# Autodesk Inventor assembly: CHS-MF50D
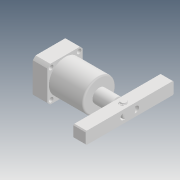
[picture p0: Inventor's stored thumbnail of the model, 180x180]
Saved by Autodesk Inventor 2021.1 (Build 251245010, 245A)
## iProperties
Created: 2019-04
Part Number: CHS-MF50D
Description: STEP AP203
Document SubType Name: Assembly
Designer: user
Title: chs-mf50d_asm.STEP
Revision Number: ÈÎºÎ
Sending System: SolidWorks 2017
Preprocessor: SwSTEP 2.0
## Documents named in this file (12)
- D:\Vault_2016\Projekty\Clamptek\Hydraulic\CHS\CHS-50\Inventor\CHS-MF50D\CHS-MF50D.iam
- D:\Vault_2016\Projekty\Clamptek\Hydraulic\CHS\CHS-50\Inventor\CHS-MF50D\CHS-MF50BT_1.ipt
- D:\Vault_2016\Projekty\Clamptek\Hydraulic\CHS\CHS-50\Inventor\CHS-MF50D\CHS-50DHSG_4.ipt
- D:\Vault_2016\Projekty\Clamptek\Hydraulic\CHS\CHS-50\Inventor\CHS-MF50D\M6_2.ipt
- D:\Vault_2016\Projekty\Clamptek\Hydraulic\CHS\CHS-50\Inventor\CHS-MF50D\PRT0002_1.ipt
- D:\Vault_2016\Projekty\Clamptek\Hydraulic\CHS\CHS-50\Inventor\CHS-MF50D\M6LM_1.ipt
- D:\Vault_2016\Projekty\Clamptek\Hydraulic\CHS\CHS-50\Inventor\CHS-MF50D\PRT0003_1.ipt
- D:\Vault_2016\Projekty\Clamptek\Hydraulic\CHS\CHS-50\Inventor\CHS-MF50D\PRT0001_1.ipt
- D:\Vault_2016\Projekty\Clamptek\Hydraulic\CHS\CHS-50\Inventor\CHS-MF50D\PRT0006_1.ipt
- D:\Vault_2016\Projekty\Clamptek\Hydraulic\CHS\CHS-50\Inventor\CHS-MF50D\CHS-50DYB_5.ipt
- D:\Vault_2016\Projekty\Clamptek\Hydraulic\CHS\CHS-50\Inventor\CHS-MF50D\ÖáÓÃµ²È¦.ipt
- D:\Vault_2016\Projekty\Clamptek\Hydraulic\CHS\CHS-50\Inventor\CHS-MF50D\Ïú.ipt
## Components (12 placed, 12 different names)
1. CHS-MF50BT_1_1
2. CHS-50DHSG_4_2
3. M6_2_3
4. PRT0002_1_4
5. M6LM_1_5
6. PRT0003_1_6
7. PRT0001_1_7
8. PRT0006_1_8
9. CHS-50DYB_5_9
10. ÖáÓÃµ²È¦_10
11. Ïú_11
12. ÖáÓÃµ²È¦_12
